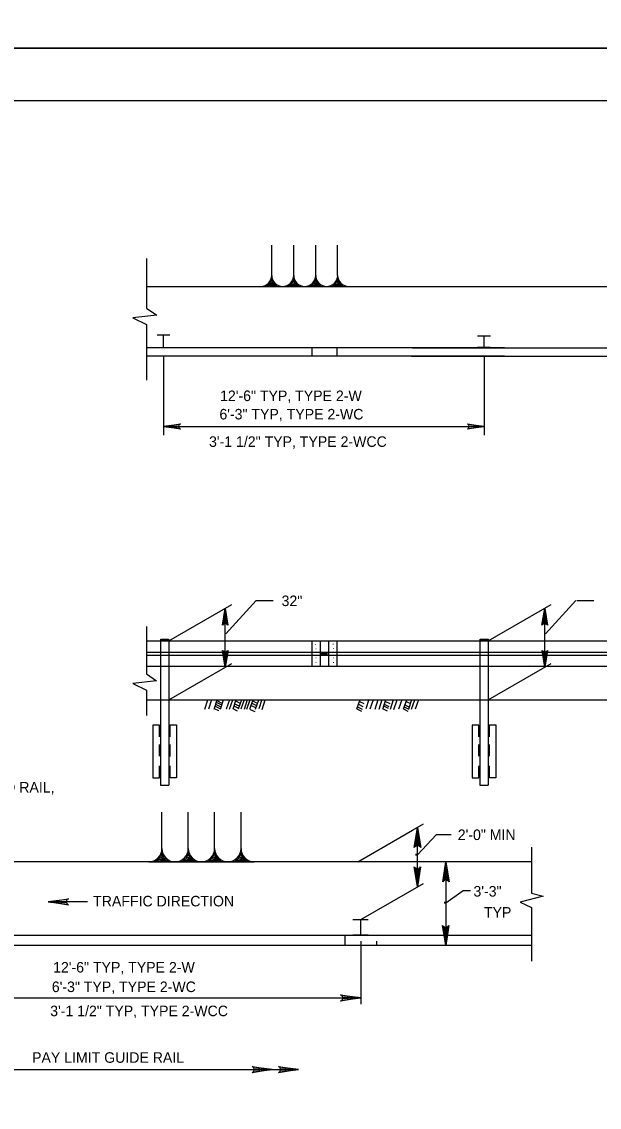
# Model space of a CAD drawing. Extents: x 637628 to 640188, y 298266 to 300751.
# Drawn here: x 638489.7 to 638654, y 298558.2 to 298867.1 of the extents above; entities that cross this region are included whole.
import ezdxf

# ---------------------------------------------------------------- set-up
doc = ezdxf.new("R2010")
doc.units = 0
for name, color, linetype in [('1', 7, 'Continuous'), ('2', 7, 'Continuous'), ('3', 7, 'Continuous'), ('PLT-BNDY', 7, 'Continuous')]:
    doc.layers.add(name, color=color, linetype=linetype)

msp = doc.modelspace()

# ---------------------------------------------------------------- linework, layer by layer
at = {"layer": '1'}
msp.add_line((638574.61, 298683.71), (638577, 298683.71), dxfattribs=at)
msp.add_lwpolyline([(639104.52, 298280.58), (639104.52, 298844.55), (638318.55, 298844.55), (638318.55, 298280.58), (639104.52, 298280.58), (639104.52, 298306.93), (638904.53, 298306.93), (638904.53, 298371.61), (639104.52, 298371.61), (639104.52, 298400.57), (638904.53, 298400.57), (638904.53, 298280.58), (638983.33, 298280.58), (638983.33, 298306.93), (638983.33, 298280.58), (639060.33, 298280.58), (639060.33, 298306.93), (639060.33, 298294.62), (639104.52, 298294.62)], dxfattribs=at)
at = {"layer": '2'}
for p, q in [((638560.83, 298794.87), (638560.83, 298803.49)), ((638567.08, 298794.87), (638567.08, 298803.49)), ((638573.33, 298794.87), (638573.33, 298803.49)), ((638579.58, 298794.87), (638579.58, 298803.49)), ((638525.21, 298799.72), (638525.21, 298785.58)), ((638525.21, 298791.71), (638711.87, 298791.71)), ((638525.21, 298780.94), (638525.21, 298765.09)), ((638528.22, 298777.95), (638531.87, 298777.95)), ((638530.08, 298774.38), (638530.08, 298777.84)), ((638619.39, 298777.65), (638623.04, 298777.65)), ((638621.24, 298774.08), (638621.24, 298777.53)), ((638621.24, 298774.08), (638621.24, 298777.53)), ((638627.01, 298774.24), (638525.21, 298774.24)), ((638528.22, 298774.38), (638531.87, 298774.38)), ((638572.22, 298774.24), (638572.22, 298771.87)), ((638579.39, 298774.24), (638579.39, 298771.87)), ((638712.78, 298774.21), (638600.83, 298774.21)), ((638619.35, 298774.46), (638623, 298774.46)), ((638627.01, 298771.87), (638525.21, 298771.87)), ((638530.08, 298771.88), (638530.08, 298749.39)), ((638712.68, 298771.84), (638600.54, 298771.84)), ((638621.24, 298771.58), (638621.24, 298749.39)), ((638530.08, 298751.89), (638621.24, 298751.89)), ((638531.58, 298690.89), (638549.48, 298701.22)), ((638547.72, 298692.94), (638556.37, 298702.43)), ((638556.37, 298702.43), (638561.26, 298702.43)), ((638622.42, 298690.89), (638640.32, 298701.22)), ((638638.69, 298692.94), (638647.34, 298702.43)), ((638647.6, 298702.43), (638652.48, 298702.43)), ((638547.62, 298683.41), (638547.62, 298700.15)), ((638638.47, 298683.41), (638638.47, 298700.15)), ((638525.21, 298695.01), (638525.16, 298681.5)), ((638525.21, 298695.01), (638525.21, 298686.44)), ((638525.21, 298690.89), (638803.1, 298690.89)), ((638529.18, 298690.89), (638529.18, 298683.71)), ((638531.58, 298690.89), (638531.58, 298683.71)), ((638572.22, 298690.89), (638572.22, 298683.71)), ((638574.61, 298690.89), (638574.61, 298683.71)), ((638577, 298690.89), (638577, 298683.71)), ((638579.39, 298690.89), (638579.39, 298683.71)), ((638620.03, 298690.89), (638620.03, 298683.71)), ((638622.42, 298690.89), (638622.42, 298683.71)), ((638525.21, 298687.73), (638802.53, 298687.73)), ((638525.21, 298686.87), (638802.72, 298686.87)), ((638525.21, 298683.71), (638802.93, 298683.71)), ((638529.18, 298683.71), (638529.18, 298674.15)), ((638531.58, 298674.15), (638549.48, 298684.49)), ((638531.58, 298683.71), (638531.58, 298674.15)), ((638620.03, 298683.71), (638620.03, 298674.15)), ((638622.42, 298674.15), (638640.32, 298684.49)), ((638622.42, 298683.71), (638622.42, 298674.15)), ((638525.21, 298676.83), (638525.21, 298674.15)), ((638525.21, 298674.15), (638992.56, 298674.15)), ((638525.21, 298674.15), (638525.21, 298669.7)), ((638529.18, 298674.15), (638529.18, 298649.85)), ((638531.58, 298674.15), (638531.58, 298649.85)), ((638542.58, 298674.05), (638541.68, 298671.37)), ((638543.71, 298674.15), (638542.81, 298671.47)), ((638545.2, 298674.05), (638544.31, 298671.37)), ((638545.05, 298673.43), (638546.31, 298672.8)), ((638545.2, 298673.9), (638546.46, 298673.27)), ((638547.02, 298674.05), (638546.12, 298671.37)), ((638548.78, 298674.15), (638547.88, 298671.47)), ((638549.64, 298674.04), (638548.75, 298671.36)), ((638550.63, 298674.15), (638549.74, 298671.47)), ((638550.52, 298673.85), (638551.81, 298673.2)), ((638552.18, 298674.15), (638551.29, 298671.47)), ((638552.94, 298674.15), (638552.04, 298671.47)), ((638553.83, 298674.09), (638552.94, 298671.41)), ((638554.55, 298674.09), (638553.65, 298671.41)), ((638555.43, 298674.09), (638554.53, 298671.41)), ((638555.17, 298673.17), (638556.45, 298672.53)), ((638555.37, 298673.85), (638556.66, 298673.2)), ((638557.03, 298674.05), (638556.14, 298671.37)), ((638558.05, 298674.2), (638557.16, 298671.52)), ((638558.89, 298674), (638558, 298671.32)), ((638585.84, 298674.15), (638584.94, 298671.47)), ((638585.78, 298673.69), (638587.07, 298673.05)), ((638588.46, 298674.2), (638587.57, 298671.52)), ((638589.64, 298674.15), (638588.75, 298671.47)), ((638591.01, 298674.09), (638590.11, 298671.41)), ((638592.17, 298674.09), (638591.28, 298671.41)), ((638593.22, 298674.09), (638592.32, 298671.41)), ((638593.16, 298673.69), (638594.45, 298673.05)), ((638595.39, 298674.09), (638594.5, 298671.41)), ((638596.41, 298674), (638595.51, 298671.32)), ((638597.81, 298674.15), (638596.92, 298671.47)), ((638599.16, 298674.09), (638598.26, 298671.41)), ((638599.04, 298673.69), (638600.33, 298673.05)), ((638600.6, 298674.15), (638599.71, 298671.47)), ((638601.42, 298674.04), (638600.53, 298671.36)), ((638602.56, 298674.15), (638601.67, 298671.47)), ((638620.03, 298674.15), (638620.03, 298649.85)), ((638622.42, 298674.15), (638622.42, 298649.85)), ((638544.47, 298671.67), (638545.66, 298671.08)), ((638544.73, 298672.35), (638546.02, 298671.7)), ((638544.84, 298672.87), (638546.35, 298672.12)), ((638549.74, 298671.67), (638551.02, 298671.03)), ((638550.05, 298672.4), (638551.34, 298671.76)), ((638550.26, 298673.02), (638551.54, 298672.38)), ((638554.7, 298671.41), (638555.98, 298670.77)), ((638554.96, 298672.55), (638556.24, 298671.91)), ((638585.06, 298671.52), (638586.34, 298670.88)), ((638585.26, 298672.14), (638586.55, 298671.5)), ((638585.47, 298672.91), (638586.75, 298672.27)), ((638592.34, 298671.67), (638593.62, 298671.03)), ((638592.64, 298672.4), (638593.93, 298671.76)), ((638592.85, 298672.91), (638594.13, 298672.27)), ((638598.28, 298671.52), (638599.56, 298670.88)), ((638598.52, 298672.09), (638599.81, 298671.44)), ((638598.69, 298672.7), (638599.97, 298672.06)), ((638531.73, 298666.99), (638531.73, 298663.62)), ((638622.57, 298666.99), (638622.57, 298663.62)), ((638529.06, 298666.94), (638529.06, 298663.57)), ((638619.91, 298666.94), (638619.91, 298663.57)), ((638529.04, 298661.46), (638529.04, 298658.1)), ((638531.68, 298661.44), (638531.68, 298658.07)), ((638619.88, 298661.46), (638619.88, 298658.1)), ((638622.53, 298661.44), (638622.53, 298658.07)), ((638529.06, 298655.34), (638529.06, 298651.97)), ((638531.75, 298655.36), (638531.75, 298652)), ((638619.91, 298655.34), (638619.91, 298651.97)), ((638622.6, 298655.36), (638622.6, 298652)), ((638529.18, 298649.85), (638531.58, 298649.85)), ((638620.03, 298649.85), (638622.42, 298649.85)), ((638529.59, 298631.81), (638529.59, 298642.14)), ((638537.09, 298631.81), (638537.09, 298642.14)), ((638544.59, 298631.81), (638544.59, 298642.14)), ((638552.09, 298631.81), (638552.09, 298642.14)), ((638585.3, 298628.04), (638600.88, 298637.03)), ((638600.88, 298637.03), (638603.99, 298638.83)), ((638602.25, 298620.87), (638602.25, 298637.82)), ((638634.69, 298632.16), (638634.69, 298623.59)), ((638634.69, 298632.16), (638634.69, 298619.08)), ((638634.69, 298628.04), (638462.97, 298628.04)), ((638610.32, 298628.04), (638610.32, 298604.19)), ((638586.15, 298611.58), (638603.99, 298621.88)), ((638508.46, 298616.62), (638497.24, 298616.62)), ((638634.69, 298615.04), (638634.69, 298604.19)), ((638583.88, 298611.58), (638588.26, 298611.58)), ((638586.15, 298607.3), (638586.15, 298611.58)), ((638634.69, 298608.31), (638634.69, 298599.75)), ((638634.69, 298607.04), (638462.97, 298607.04)), ((638581.74, 298604.3), (638581.74, 298606.89)), ((638583.88, 298607.3), (638588.26, 298607.3)), ((638586.15, 298605.5), (638586.15, 298587.49)), ((638590.69, 298604.19), (638590.69, 298605.42)), ((638634.69, 298604.19), (638462.97, 298604.19)), ((638476.24, 298589.29), (638586.15, 298589.29)), ((638476.24, 298568.9), (638568.48, 298568.9))]:
    msp.add_line(p, q, dxfattribs=at)
for points in [[(638559.3, 298791.92), (638560.17, 298792.47), (638560.8, 298793.7)], [(638559.37, 298792.01), (638562.22, 298791.99), (638559.93, 298792.3), (638561.64, 298792.4), (638560.26, 298792.62), (638561.23, 298792.88), (638560.68, 298793.1), (638561.09, 298793.25), (638560.75, 298793.54), (638560.8, 298793.85), (638561.47, 298792.35), (638562.27, 298791.96)], [(638565.61, 298791.89), (638566.48, 298792.45), (638567.11, 298793.68)], [(638565.7, 298792.04), (638568.56, 298792.01), (638566.26, 298792.33), (638567.98, 298792.42), (638566.6, 298792.64), (638567.57, 298792.91), (638567.01, 298793.12), (638567.42, 298793.27), (638567.08, 298793.56), (638567.13, 298793.87), (638567.81, 298792.37), (638568.61, 298791.99)], [(638571.89, 298792.06), (638574.74, 298792.04), (638572.45, 298792.35), (638574.17, 298792.45), (638572.79, 298792.67), (638573.75, 298792.93), (638573.2, 298793.15), (638573.61, 298793.29), (638573.27, 298793.59), (638573.32, 298793.9), (638573.99, 298792.4), (638574.79, 298792.01)], [(638571.89, 298792.01), (638572.76, 298792.57), (638573.39, 298793.8)], [(638578.08, 298791.96), (638578.95, 298792.52), (638579.58, 298793.75)], [(638578.18, 298792.04), (638581.03, 298792.01), (638578.73, 298792.33), (638580.45, 298792.42), (638579.07, 298792.64), (638580.04, 298792.91), (638579.48, 298793.12), (638579.89, 298793.27), (638579.56, 298793.56), (638579.6, 298793.87), (638580.28, 298792.37), (638581.08, 298791.99)], [(638557.71, 298791.75), (638582.71, 298791.75)], [(638525.21, 298785.58), (638528.1, 298783.61), (638521.34, 298782.82), (638525.21, 298780.94)], [(638534.62, 298751.32), (638534.45, 298751.65), (638530.08, 298751.89), (638534.62, 298751.32), (638534.85, 298751.12), (638530.08, 298751.89), (638534.44, 298752.1), (638534.61, 298752.43), (638530.08, 298751.89), (638534.85, 298752.65), (638534.61, 298752.43)], [(638616.71, 298752.46), (638616.87, 298752.13), (638621.24, 298751.89), (638616.71, 298752.46), (638616.47, 298752.66), (638621.24, 298751.89), (638616.88, 298751.67), (638616.72, 298751.35), (638621.24, 298751.89), (638616.47, 298751.13), (638616.72, 298751.35)], [(638547.05, 298695.61), (638547.38, 298695.78), (638547.62, 298700.15), (638547.05, 298695.61), (638546.85, 298695.37), (638547.62, 298700.15), (638547.84, 298695.78), (638548.16, 298695.62), (638547.62, 298700.15), (638548.38, 298695.37), (638548.16, 298695.62)], [(638637.9, 298695.61), (638638.23, 298695.78), (638638.47, 298700.15), (638637.9, 298695.61), (638637.7, 298695.37), (638638.47, 298700.15), (638638.68, 298695.78), (638639.01, 298695.62), (638638.47, 298700.15), (638639.23, 298695.37), (638639.01, 298695.62)], [(638548.19, 298687.95), (638547.86, 298687.78), (638547.62, 298683.41), (638548.19, 298687.95), (638548.39, 298688.19), (638547.62, 298683.41), (638547.41, 298687.78), (638547.08, 298687.94), (638547.62, 298683.41), (638546.86, 298688.19), (638547.08, 298687.94)], [(638639.04, 298687.95), (638638.71, 298687.78), (638638.47, 298683.41), (638639.04, 298687.95), (638639.24, 298688.19), (638638.47, 298683.41), (638638.25, 298687.78), (638637.93, 298687.94), (638638.47, 298683.41), (638637.71, 298688.19), (638637.93, 298687.94)], [(638525.16, 298681.5), (638528.06, 298679.54), (638521.29, 298678.74), (638525.16, 298676.86)], [(638528.9, 298663.6), (638528.9, 298666.96), (638527.04, 298666.96), (638527.04, 298651.96), (638528.9, 298651.96), (638528.9, 298655.34)], [(638531.89, 298663.64), (638531.89, 298666.97), (638533.75, 298666.97), (638533.75, 298651.97), (638531.89, 298651.97), (638531.89, 298655.34)], [(638619.74, 298663.56), (638619.74, 298666.96), (638617.88, 298666.96), (638617.88, 298651.96), (638619.74, 298651.96), (638619.74, 298655.37)], [(638622.73, 298663.62), (638622.73, 298666.97), (638624.59, 298666.97), (638624.59, 298651.97), (638622.73, 298651.97), (638622.73, 298655.34)], [(638528.9, 298658.07), (638528.9, 298661.46)], [(638531.89, 298658.04), (638531.89, 298661.43)], [(638619.74, 298658.11), (638619.74, 298661.45)], [(638622.73, 298658.08), (638622.73, 298661.45)], [(638601.63, 298632.36), (638602.02, 298632.57), (638602.25, 298637.82), (638601.63, 298632.36), (638601.39, 298632.08), (638602.25, 298637.82), (638602.57, 298632.58), (638602.96, 298632.4), (638602.25, 298637.82), (638603.22, 298632.1), (638602.96, 298632.4)], [(638611.85, 298635.67), (638607.59, 298635.67), (638602.25, 298630)], [(638527.75, 298628.26), (638528.79, 298628.92), (638529.55, 298630.4)], [(638527.84, 298628.37), (638531.26, 298628.34), (638528.5, 298628.72), (638530.56, 298628.84), (638528.91, 298629.1), (638530.07, 298629.42), (638529.4, 298629.68), (638529.89, 298629.85), (638529.49, 298630.2), (638529.55, 298630.58), (638530.36, 298628.78), (638531.32, 298628.31)], [(638535.32, 298628.23), (638536.36, 298628.89), (638537.12, 298630.37)], [(638535.44, 298628.4), (638538.86, 298628.37), (638536.1, 298628.75), (638538.16, 298628.86), (638536.51, 298629.13), (638537.67, 298629.44), (638537, 298629.71), (638537.5, 298629.88), (638537.09, 298630.23), (638537.15, 298630.61), (638537.96, 298628.81), (638538.92, 298628.34)], [(638542.86, 298628.43), (638546.29, 298628.4), (638543.53, 298628.78), (638545.59, 298628.89), (638543.94, 298629.15), (638545.1, 298629.47), (638544.43, 298629.73), (638544.92, 298629.91), (638544.52, 298630.26), (638544.57, 298630.63), (638545.39, 298628.84), (638546.34, 298628.37)], [(638542.86, 298628.37), (638543.91, 298629.04), (638544.66, 298630.52)], [(638550.29, 298628.31), (638551.33, 298628.98), (638552.09, 298630.46)], [(638550.4, 298628.4), (638553.83, 298628.37), (638551.07, 298628.75), (638553.13, 298628.86), (638551.48, 298629.13), (638552.64, 298629.44), (638551.97, 298629.71), (638552.46, 298629.88), (638552.06, 298630.23), (638552.12, 298630.61), (638552.93, 298628.81), (638553.89, 298628.34)], [(638525.84, 298628.06), (638555.84, 298628.06)], [(638609.69, 298622.58), (638610.09, 298622.79), (638610.32, 298628.04), (638609.69, 298622.58), (638609.46, 298622.3), (638610.32, 298628.04), (638610.63, 298622.8), (638611.03, 298622.61), (638610.32, 298628.04), (638611.29, 298622.32), (638611.03, 298622.61)], [(638602.93, 298626.32), (638602.54, 298626.12), (638602.25, 298620.87), (638602.93, 298626.32), (638603.17, 298626.6), (638602.25, 298620.87), (638601.99, 298626.11), (638601.6, 298626.3), (638602.25, 298620.87), (638601.34, 298626.6), (638601.6, 298626.3)], [(638617.38, 298619.82), (638615.3, 298619.82), (638610.32, 298616.25)], [(638634.69, 298619.08), (638638.01, 298618.22), (638631.48, 298616.52), (638634.69, 298615.04)], [(638502.69, 298615.94), (638502.49, 298616.33), (638497.24, 298616.62), (638502.69, 298615.94), (638502.97, 298615.7), (638497.24, 298616.62), (638502.48, 298616.88), (638502.67, 298617.27), (638497.24, 298616.62), (638502.97, 298617.53), (638502.67, 298617.27)], [(638611, 298609.64), (638610.61, 298609.44), (638610.32, 298604.19), (638611, 298609.64), (638611.24, 298609.92), (638610.32, 298604.19), (638610.06, 298609.44), (638609.67, 298609.63), (638610.32, 298604.19), (638609.41, 298609.92), (638609.67, 298609.63)], [(638580.7, 298589.98), (638580.91, 298589.58), (638586.15, 298589.29), (638580.7, 298589.98), (638580.42, 298590.22), (638586.15, 298589.29), (638580.91, 298589.03), (638580.72, 298588.64), (638586.15, 298589.29), (638580.42, 298588.38), (638580.72, 298588.64)], [(638555.53, 298569.59), (638555.73, 298569.19), (638560.98, 298568.9), (638555.53, 298569.59), (638555.25, 298569.83), (638560.98, 298568.9), (638555.74, 298568.64), (638555.55, 298568.25), (638560.98, 298568.9), (638555.25, 298567.99), (638555.55, 298568.25)], [(638563.03, 298569.59), (638563.23, 298569.19), (638568.48, 298568.9), (638563.03, 298569.59), (638562.75, 298569.83), (638568.48, 298568.9), (638563.24, 298568.64), (638563.05, 298568.25), (638568.48, 298568.9), (638562.75, 298567.99), (638563.05, 298568.25)]]:
    msp.add_lwpolyline(points, dxfattribs=at)
for points in [[(638529.23, 298690.95), (638529.23, 298691.34), (638531.49, 298691.34), (638531.49, 298690.95)], [(638620.12, 298690.98), (638620.12, 298691.36), (638622.37, 298691.36), (638622.37, 298690.98)], [(638574.99, 298686.91), (638574.99, 298687.69), (638576.46, 298687.69), (638576.46, 298686.91)], [(638575.01, 298686.93), (638575.01, 298687.67), (638576.41, 298687.67), (638576.41, 298686.93)], [(638575.04, 298686.96), (638575.04, 298687.66), (638576.37, 298687.66), (638576.37, 298686.96)], [(638575.06, 298686.97), (638575.06, 298687.64), (638576.33, 298687.64), (638576.33, 298686.97)], [(638575.09, 298686.99), (638575.09, 298687.63), (638576.29, 298687.63), (638576.29, 298686.99)], [(638575.11, 298687.01), (638575.11, 298687.61), (638576.25, 298687.61), (638576.25, 298687.01)], [(638575.14, 298687.03), (638575.14, 298687.6), (638576.22, 298687.6), (638576.22, 298687.03)], [(638575.15, 298687.04), (638575.15, 298687.58), (638576.18, 298687.58), (638576.18, 298687.04)], [(638575.17, 298687.06), (638575.17, 298687.57), (638576.15, 298687.57), (638576.15, 298687.06)], [(638575.2, 298687.07), (638575.2, 298687.56), (638576.12, 298687.56), (638576.12, 298687.07)], [(638575.22, 298687.08), (638575.22, 298687.54), (638576.1, 298687.54), (638576.1, 298687.08)], [(638575.25, 298687.09), (638575.25, 298687.53), (638576.08, 298687.53), (638576.08, 298687.09)], [(638575.27, 298687.1), (638575.27, 298687.52), (638576.06, 298687.52), (638576.06, 298687.1)], [(638575.29, 298687.11), (638575.29, 298687.51), (638576.05, 298687.51), (638576.05, 298687.11)], [(638575.31, 298687.12), (638575.31, 298687.5), (638576.03, 298687.5), (638576.03, 298687.12)], [(638575.33, 298687.13), (638575.33, 298687.49), (638576.01, 298687.49), (638576.01, 298687.13)], [(638575.35, 298687.13), (638575.35, 298687.48), (638576, 298687.48), (638576, 298687.13)], [(638575.36, 298687.14), (638575.36, 298687.47), (638575.98, 298687.47), (638575.98, 298687.14)], [(638575.38, 298687.15), (638575.38, 298687.46), (638575.97, 298687.46), (638575.97, 298687.15)], [(638575.4, 298687.16), (638575.4, 298687.45), (638575.95, 298687.45), (638575.95, 298687.16)], [(638575.41, 298687.16), (638575.41, 298687.44), (638575.94, 298687.44), (638575.94, 298687.16)], [(638575.43, 298687.17), (638575.43, 298687.43), (638575.93, 298687.43), (638575.93, 298687.17)], [(638575.44, 298687.18), (638575.44, 298687.43), (638575.92, 298687.43), (638575.92, 298687.18)], [(638575.45, 298687.18), (638575.45, 298687.42), (638575.91, 298687.42), (638575.91, 298687.18)], [(638575.47, 298687.19), (638575.47, 298687.41), (638575.9, 298687.41), (638575.9, 298687.19)], [(638575.48, 298687.19), (638575.48, 298687.41), (638575.89, 298687.41), (638575.89, 298687.19)], [(638575.49, 298687.2), (638575.49, 298687.4), (638575.88, 298687.4), (638575.88, 298687.2)], [(638575.5, 298687.2), (638575.5, 298687.4), (638575.87, 298687.4), (638575.87, 298687.2)], [(638575.51, 298687.21), (638575.51, 298687.39), (638575.86, 298687.39), (638575.86, 298687.21)], [(638575.52, 298687.21), (638575.52, 298687.39), (638575.85, 298687.39), (638575.85, 298687.21)], [(638575.53, 298687.22), (638575.53, 298687.38), (638575.84, 298687.38), (638575.84, 298687.22)], [(638575.54, 298687.22), (638575.54, 298687.38), (638575.84, 298687.38), (638575.84, 298687.22)], [(638575.54, 298687.22), (638575.54, 298687.37), (638575.83, 298687.37), (638575.83, 298687.22)], [(638575.55, 298687.23), (638575.55, 298687.37), (638575.82, 298687.37), (638575.82, 298687.23)], [(638575.56, 298687.23), (638575.56, 298687.37), (638575.82, 298687.37), (638575.82, 298687.23)]]:
    msp.add_lwpolyline(points, close=True, dxfattribs=at)
for centre, radius, start, end in [((638557.71, 298794.88), 3.13, 270, 0), ((638563.96, 298794.88), 3.13, 180, 0), ((638570.21, 298794.88), 3.13, 180, 0), ((638576.46, 298794.88), 3.13, 180, 0), ((638582.71, 298794.88), 3.13, 180, 270), ((638525.84, 298631.81), 3.75, 270, 0), ((638533.34, 298631.81), 3.75, 180, 0), ((638540.84, 298631.81), 3.75, 180, 0), ((638548.34, 298631.81), 3.75, 180, 0), ((638555.84, 298631.81), 3.75, 180, 270)]:
    msp.add_arc(centre, radius, start, end, dxfattribs=at)
at = {"layer": 'PLT-BNDY'}
for points in [[(638278.52, 299453.58), (639119.52, 299453.58), (639119.52, 298859.58), (638278.52, 298859.58)], [(638278.52, 298859.58), (639119.52, 298859.58), (639119.52, 298265.58), (638278.52, 298265.58)]]:
    msp.add_lwpolyline(points, close=True, dxfattribs=at)

# ---------------------------------------------------------------- texts
at = {"layer": '3'}
for s, height, p in [('12\'-6" TYP, TYPE 2-W', 3, (638546.13, 298759.13)), ('6\'-3" TYP, TYPE 2-WC', 3, (638545.94, 298753.9)), ('3\'-1 1/2" TYP, TYPE 2-WCC', 3, (638542.99, 298746.1)), ('32"', 3, (638563.63, 298700.8)), ('.', 1.72, (638573.03, 298689.72)), ('.', 1.72, (638573.11, 298688.51)), ('.', 1.72, (638577.99, 298689.84)), ('.', 1.72, (638578.02, 298688.57)), ('.', 1.72, (638573.13, 298685.92)), ('.', 1.72, (638578.02, 298685.95)), ('.', 1.72, (638573.11, 298684.6)), ('.', 1.72, (638578.09, 298684.61)), ('SHOP CURVED RAIL,', 2.9999, (638458.47, 298647.74)), ('2\'-0" MIN', 3, (638613.75, 298634.23)), ('3\'-3"', 3, (638618.21, 298618.15)), ('TRAFFIC DIRECTION', 2.9999, (638510.02, 298615.35)), ('TYP', 3, (638621.19, 298612.15)), ('12\'-6" TYP, TYPE 2-W', 2.9999, (638498.63, 298596.53)), ('6\'-3" TYP, TYPE 2-WC', 2.9999, (638498.27, 298590.97)), ('3\'-1 1/2" TYP, TYPE 2-WCC', 2.9999, (638497.81, 298584.11)), ('PAY LIMIT GUIDE RAIL', 2.9999, (638492.65, 298570.85))]:
    msp.add_text(s, height=height, dxfattribs=at).set_placement(p)
for p in [(638602.6, 298630.35), (638610.77, 298616.68)]:
    msp.add_text('.', height=3.6, rotation=180, dxfattribs=at).set_placement(p)

doc.saveas('drawing.dxf')
